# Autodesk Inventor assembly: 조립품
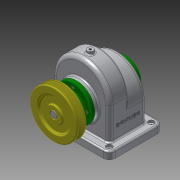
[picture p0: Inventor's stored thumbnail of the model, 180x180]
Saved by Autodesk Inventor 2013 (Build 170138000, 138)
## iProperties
Created: 2017-11
Part Number: 조립품
Document SubType Name: Assembly
Designer: Administrator
Author: Administrator
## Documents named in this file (14)
- C:\Users\Administrator\Desktop\471107V1016\조립품.iam
- C:\Users\Administrator\Desktop\471107V1016\본체.ipt
- C:\Users\Administrator\Desktop\471107V1016\V-벨트풀리.ipt
- C:\Users\Administrator\Desktop\471107V1016\뒤커버.ipt
- C:\Users\Administrator\Desktop\471107V1016\멈춤나사 - M4 x 10.ipt
- 멈춤나사 - M4 x 10.ipt
- C:\Users\Administrator\Desktop\471107V1016\베어링 6002.ipt
- C:\Users\Administrator\Desktop\471107V1016\볼트 M3 x 8.ipt
- C:\Users\Administrator\Desktop\471107V1016\스퍼기어.ipt
- C:\Users\Administrator\Desktop\471107V1016\앞커버.ipt
- C:\Users\Administrator\Desktop\471107V1016\오일 실 15 30 7.ipt
- C:\Users\Administrator\Desktop\471107V1016\축.ipt
- C:\Users\Administrator\Desktop\471107V1016\키 - 5 x 5 x 18.ipt
- C:\Users\Administrator\Desktop\471107V1016\키 - 6 x 6 x 22.ipt
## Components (1 placed, 1 different names)
1. V-벨트풀리:1 — 각도:4, 각도:5
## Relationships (2: Angle 2)
- 각도:4 [Angle]: V-벨트풀리:1
- 각도:5 [Angle]: V-벨트풀리:1
